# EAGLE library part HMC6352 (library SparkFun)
HMC6352 This is the compass module from Honeywell. Works very well. Schematic and footprint are production proven. Spark Fun Electronics SKU : IC-HMC6352
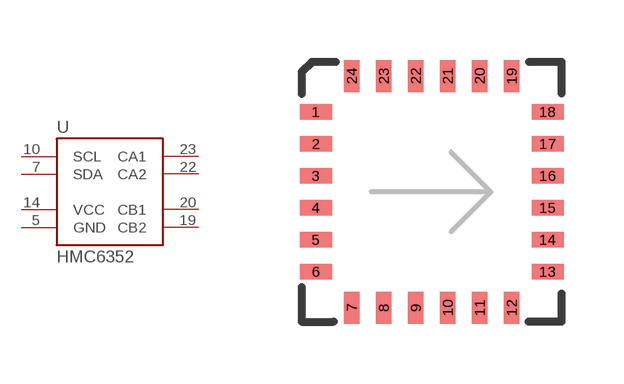
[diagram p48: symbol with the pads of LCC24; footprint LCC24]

Designator prefix -

## HMC6352  [LCC24]
5  GND
7  SDA
10  SCL
14  VCC
19  CB2
20  CB1
22  CA2
23  CA1

## Footprint LCC24 (pad centres in mm)
smd 0.8 x 0.38: 1 -2.9,2.01; 2 -2.9,1.21; 3 -2.9,0.41; 4 -2.9,-0.39; 5 -2.9,-1.19; 6 -2.9,-1.99; 13 2.9,-1.99; 14 2.9,-1.19; 15 2.9,-0.39; 16 2.9,0.41; 17 2.9,1.21; 18 2.9,2.01
smd 0.38 x 0.8: 7 -2,-2.89; 8 -1.2,-2.89; 9 -0.4,-2.89; 10 0.4,-2.89; 11 1.2,-2.89; 12 2,-2.89; 19 2,2.91; 20 1.2,2.91; 21 0.4,2.91; 22 -0.4,2.91; 23 -1.2,2.91; 24 -2,2.91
